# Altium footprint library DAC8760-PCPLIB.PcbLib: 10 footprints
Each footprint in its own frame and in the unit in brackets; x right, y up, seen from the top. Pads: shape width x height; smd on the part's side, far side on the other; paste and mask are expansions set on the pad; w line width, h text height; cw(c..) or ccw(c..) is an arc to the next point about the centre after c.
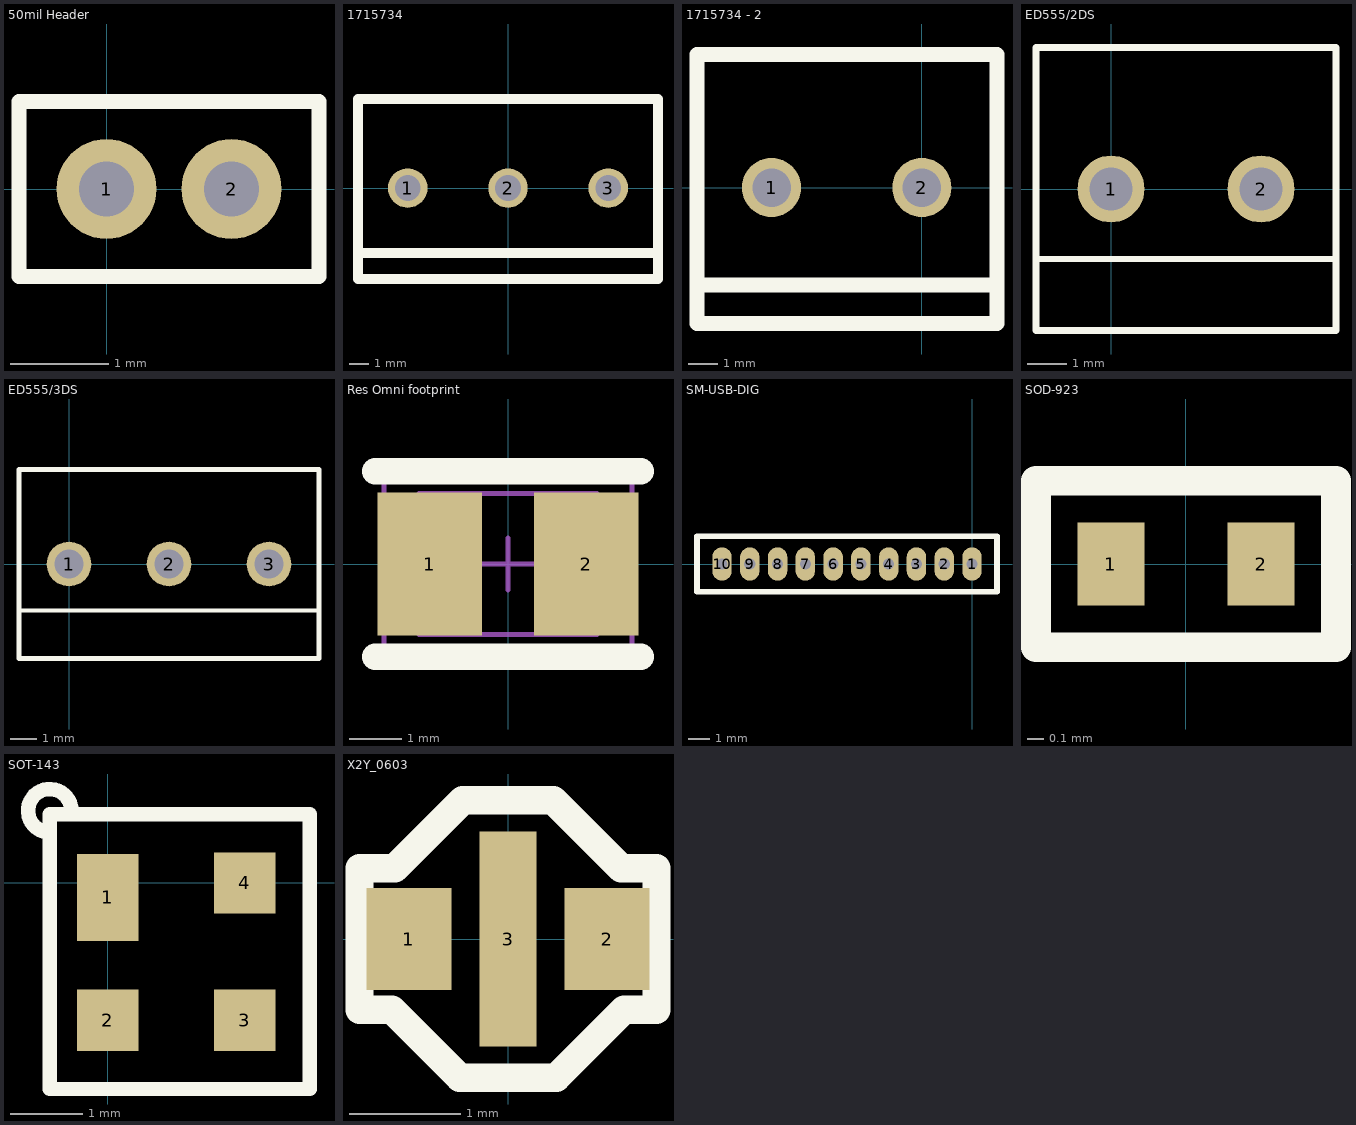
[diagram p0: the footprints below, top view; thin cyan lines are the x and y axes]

## 50mil Header [mil]
pads (2):
  round 40 hole 22: 1(0,0) 2(50,0)
Top Overlay:
  lines w6: -35,-35 85,-35 85,35 -35,35 -35,-35

## 1715734 [mm] "CONN TERM BLOCK 3POS 5.08MM PCB"
height 13.8
pads (3):
  round 2 hole 1.3: 1(-5.08,0) 2(0,0) 3(5.08,0)
Top Overlay:
  lines w0.508: -7.6,-3.3 7.6,-3.3 ; -7.6,-4.6 -0.2,-4.6 7.6,-4.6 7.6,4.5 -7.6,4.5 -7.6,-4.6
M5 Assembly Top:
  text ".Designator" at -7.4,5.2 h1.02
3D body: height 9, standoff 0, extent -7.6,-4.6 7.6,4.5

## 1715734 - 2 [mm] "CONN TERM BLOCK 2POS 5.08MM PCB"
height 13.8
pads (2):
  round 2 hole 1.3: 1(-5.08,0) 2(0,0)
Top Overlay:
  lines w0.508: -7.6,-3.3 2.54,-3.3 ; -7.6,-4.6 -0.2,-4.6 2.54,-4.6 2.54,4.5 -7.6,4.5 -7.6,-4.6
M5 Assembly Top:
  text ".Designator" at -7.4,5.2 h1.02
3D body: height 9, standoff 0, extent -7.6,-4.6 2.54,4.5

## ED555/2DS [mm] "TERMINAL BLOCK 3.5MM 2POS PCB"
pads (2):
  round 1.7 hole 1.1: 1(0,0) 2(3.81,0)
Top Overlay:
  lines w0.152: -1.905,-1.778 5.715,-1.778
  lines w0.178: -1.905,-3.6 -1.905,0 -1.905,3.6 1.905,3.6 5.715,3.6 5.715,0 5.715,-3.6 1.905,-3.6 -1.905,-3.6
M5 Assembly Top:
  text ".Designator" at -2.794,4.572 h1.02
3D body: height 8.52, standoff -3.48, extent -1.905,-3.599 5.715,3.701

## ED555/3DS [mm] "TERMINAL BLOCK 3.5MM 3POS PCB"
pads (3):
  round 1.7 hole 1.1: 1(0,0) 2(3.81,0) 3(7.62,0)
Top Overlay:
  lines w0.152: -1.905,-1.778 9.525,-1.778
  lines w0.178: -1.905,-3.6 1.905,-3.6 5.715,-3.6 9.525,-3.6 9.525,0 9.525,3.6 5.715,3.6 1.905,3.6 -1.905,3.6 -1.905,0 -1.905,-3.6
M5 Assembly Top:
  text ".Designator" at -2.286,4.572 h1.02
3D body: height 6.35, standoff 0, extent -1.905,-3.7 9.525,3.6

## Res Omni footprint [mm] "Chip Resistor, 2-Leads, 0603-1210"
height 0.6
pads (2):
  rect 2x2.75 smd: 1(-1.5,0) 2(1.5,0)
Top Overlay:
  lines w0.508: -2.54,-1.778 2.54,-1.778 ; -2.54,1.778 2.54,1.778
M13 Component Bodies Top:
  lines w0.1: -1.7,-1.35 1.7,-1.35 1.7,1.35 -1.7,1.35 -1.7,-1.35
M15  Courtyards Top:
  lines w0.1: -0.5,0 0.5,0 ; 0,-0.5 0,0.5 ; -2.375,-1.625 2.375,-1.625 2.375,1.625 -2.375,1.625 -2.375,-1.625
3D body: height 0.6, standoff 0, extent -1.7,-1.35 1.7,1.35

## SM-USB-DIG [mil]
pads (10):
  oval 35x60 hole 20: 1(0,0) 2(-50,0) 3(-100,0) 4(-150,0) 5(-200,0) 6(-250,0) 7(-300,0) 8(-350,0) 9(-400,0) 10(-450,0)
Top Overlay:
  lines w10: -495,-50 45,-50 45,50 -495,50 -495,-50
3D body: height 87, standoff -110.51, extent -482.5,-8.01 32.5,210

## SOD-923 [mm]
pads (2):
  rect 0.4x0.5 smd: 1(-0.45,0) 2(0.45,0)
Top Overlay:
  lines w0.178: -0.9,-0.5 0.9,-0.5 0.9,0.5 -0.9,0.5 -0.9,0 -0.9,-0.5

## SOT-143 [mm]
pads (4):
  rect 0.85x1.2 smd: 1(0,-0.2)
  rect 0.85x0.85 smd: 2(0,-1.9) 3(1.9,-1.9) 4(1.9,0)
Top Overlay:
  lines w0.2: -0.8,0.7 cw(c-0.8,1) -0.5,1 ; 0.64,0.95 1.425,0.95 ; -0.8,-2.85 2.8,-2.85 2.8,0.95 -0.8,0.95 -0.8,-2.85
3D body: height 1, standoff 0, extent -0.26,-2.41 2.16,0.51

## X2Y_0603 [mil]
pads (3):
  rect 30x36 smd: 1(-35,0) 2(35,0)
  rect 20x76 smd: 3(0,0)
Top Overlay:
  lines w10: -52.5,-25 -41,-25 -17,-49 17,-49 41,-25 52.5,-25 52.5,25 40,25 16,49 -16,49 -40,25 -52.5,25 -52.5,0 -52.5,-25
Top Solder:
  rectangle: -20,-22 20,22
